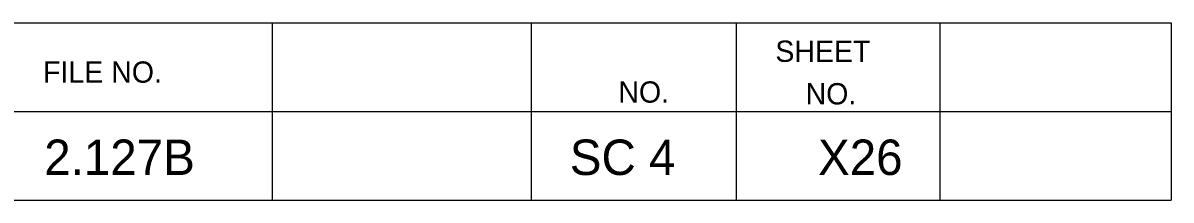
# Model space of a CAD drawing. Extents: x 1000 to 1162, y 999 to 8520.
# Drawn here: x 1145.41 to 1161.56, y 3975.05 to 3977.55 of the extents above; entities that cross this region are included whole.
import ezdxf

# ---------------------------------------------------------------- set-up
doc = ezdxf.new("R2010")
doc.units = 0
doc.layers.add('Level 20', color=7, linetype='Continuous')
doc.layers.add('Level 3', color=7, linetype='Continuous')

msp = doc.modelspace()

# ---------------------------------------------------------------- linework, layer by layer
at = {"layer": 'Level 3'}
for p, q in [((1133.055, 3977.546), (1161.555, 3977.546)), ((1133.055, 3977.546), (1161.555, 3977.546)), ((1133.055, 3977.546), (1161.555, 3977.546)), ((1133.055, 3977.546), (1161.555, 3977.546)), ((1133.055, 3977.546), (1161.555, 3977.546)), ((1133.055, 3977.546), (1161.555, 3977.546)), ((1133.055, 3977.546), (1161.555, 3977.546)), ((1133.055, 3977.546), (1161.555, 3977.546)), ((1133.055, 3977.546), (1161.555, 3977.546)), ((1133.055, 3977.546), (1161.555, 3977.546)), ((1133.055, 3977.546), (1161.555, 3977.546)), ((1133.055, 3977.546), (1161.555, 3977.546)), ((1133.055, 3977.546), (1161.555, 3977.546)), ((1133.055, 3977.546), (1161.555, 3977.546)), ((1133.055, 3977.546), (1161.555, 3977.546)), ((1133.055, 3977.546), (1161.555, 3977.546)), ((1133.055, 3977.546), (1161.555, 3977.546)), ((1133.055, 3977.546), (1161.555, 3977.546)), ((1133.055, 3977.546), (1161.555, 3977.546)), ((1133.055, 3977.546), (1161.555, 3977.546)), ((1133.055, 3977.546), (1161.555, 3977.546)), ((1133.055, 3977.546), (1161.555, 3977.546)), ((1133.055, 3977.546), (1161.555, 3977.546)), ((1133.055, 3977.546), (1161.555, 3977.546)), ((1148.913, 3977.546), (1148.913, 3975.046)), ((1148.913, 3977.546), (1148.913, 3975.046)), ((1148.913, 3977.546), (1148.913, 3975.046)), ((1148.913, 3977.546), (1148.913, 3975.046)), ((1148.913, 3977.546), (1148.913, 3975.046)), ((1148.913, 3977.546), (1148.913, 3975.046)), ((1148.913, 3977.546), (1148.913, 3975.046)), ((1148.913, 3977.546), (1148.913, 3975.046)), ((1148.913, 3977.546), (1148.913, 3975.046)), ((1148.913, 3977.546), (1148.913, 3975.046)), ((1148.913, 3977.546), (1148.913, 3975.046)), ((1148.913, 3977.546), (1148.913, 3975.046)), ((1148.913, 3977.546), (1148.913, 3975.046)), ((1148.913, 3977.546), (1148.913, 3975.046)), ((1148.913, 3977.546), (1148.913, 3975.046)), ((1148.913, 3977.546), (1148.913, 3975.046)), ((1148.913, 3977.546), (1148.913, 3975.046)), ((1148.913, 3977.546), (1148.913, 3975.046)), ((1148.913, 3977.546), (1148.913, 3975.046)), ((1148.913, 3977.546), (1148.913, 3975.046)), ((1148.913, 3977.546), (1148.913, 3975.046)), ((1148.913, 3977.546), (1148.913, 3975.046)), ((1148.913, 3977.546), (1148.913, 3975.046)), ((1148.913, 3977.546), (1148.913, 3975.046)), ((1152.554, 3977.546), (1152.554, 3975.046)), ((1152.554, 3977.546), (1152.554, 3975.046)), ((1152.554, 3977.546), (1152.554, 3975.046)), ((1152.554, 3977.546), (1152.554, 3975.046)), ((1152.554, 3977.546), (1152.554, 3975.046)), ((1152.554, 3977.546), (1152.554, 3975.046)), ((1152.554, 3977.546), (1152.554, 3975.046)), ((1152.554, 3977.546), (1152.554, 3975.046)), ((1152.554, 3977.546), (1152.554, 3975.046)), ((1152.554, 3977.546), (1152.554, 3975.046)), ((1152.554, 3977.546), (1152.554, 3975.046)), ((1152.554, 3977.546), (1152.554, 3975.046)), ((1152.554, 3977.546), (1152.554, 3975.046)), ((1152.554, 3977.546), (1152.554, 3975.046)), ((1152.554, 3977.546), (1152.554, 3975.046)), ((1152.554, 3977.546), (1152.554, 3975.046)), ((1152.554, 3977.546), (1152.554, 3975.046)), ((1152.554, 3977.546), (1152.554, 3975.046)), ((1152.554, 3977.546), (1152.554, 3975.046)), ((1152.554, 3977.546), (1152.554, 3975.046)), ((1152.554, 3977.546), (1152.554, 3975.046)), ((1152.554, 3977.546), (1152.554, 3975.046)), ((1152.554, 3977.546), (1152.554, 3975.046)), ((1152.554, 3977.546), (1152.554, 3975.046)), ((1155.44, 3977.546), (1155.44, 3975.046)), ((1155.44, 3977.546), (1155.44, 3975.046)), ((1155.44, 3977.546), (1155.44, 3975.046)), ((1155.44, 3977.546), (1155.44, 3975.046)), ((1155.44, 3977.546), (1155.44, 3975.046)), ((1155.44, 3977.546), (1155.44, 3975.046)), ((1155.44, 3977.546), (1155.44, 3975.046)), ((1155.44, 3977.546), (1155.44, 3975.046)), ((1155.44, 3977.546), (1155.44, 3975.046)), ((1155.44, 3977.546), (1155.44, 3975.046)), ((1155.44, 3977.546), (1155.44, 3975.046)), ((1155.44, 3977.546), (1155.44, 3975.046)), ((1155.44, 3977.546), (1155.44, 3975.046)), ((1155.44, 3977.546), (1155.44, 3975.046)), ((1155.44, 3977.546), (1155.44, 3975.046)), ((1155.44, 3977.546), (1155.44, 3975.046)), ((1155.44, 3977.546), (1155.44, 3975.046)), ((1155.44, 3977.546), (1155.44, 3975.046)), ((1155.44, 3977.546), (1155.44, 3975.046)), ((1155.44, 3977.546), (1155.44, 3975.046)), ((1155.44, 3977.546), (1155.44, 3975.046)), ((1155.44, 3977.546), (1155.44, 3975.046)), ((1155.44, 3977.546), (1155.44, 3975.046)), ((1155.44, 3977.546), (1155.44, 3975.046)), ((1158.305, 3977.546), (1158.305, 3975.046)), ((1158.305, 3977.546), (1158.305, 3975.046)), ((1158.305, 3977.546), (1158.305, 3975.046)), ((1158.305, 3977.546), (1158.305, 3975.046)), ((1158.305, 3977.546), (1158.305, 3975.046)), ((1158.305, 3977.546), (1158.305, 3975.046)), ((1158.305, 3977.546), (1158.305, 3975.046)), ((1158.305, 3977.546), (1158.305, 3975.046)), ((1158.305, 3977.546), (1158.305, 3975.046)), ((1158.305, 3977.546), (1158.305, 3975.046)), ((1158.305, 3977.546), (1158.305, 3975.046)), ((1158.305, 3977.546), (1158.305, 3975.046)), ((1158.305, 3977.546), (1158.305, 3975.046)), ((1158.305, 3977.546), (1158.305, 3975.046)), ((1158.305, 3977.546), (1158.305, 3975.046)), ((1158.305, 3977.546), (1158.305, 3975.046)), ((1158.305, 3977.546), (1158.305, 3975.046)), ((1158.305, 3977.546), (1158.305, 3975.046)), ((1158.305, 3977.546), (1158.305, 3975.046)), ((1158.305, 3977.546), (1158.305, 3975.046)), ((1158.305, 3977.546), (1158.305, 3975.046)), ((1158.305, 3977.546), (1158.305, 3975.046)), ((1158.305, 3977.546), (1158.305, 3975.046)), ((1158.305, 3977.546), (1158.305, 3975.046)), ((1161.555, 3977.546), (1161.555, 3975.046)), ((1161.555, 3977.546), (1161.555, 3975.046)), ((1161.555, 3977.546), (1161.555, 3975.046)), ((1161.555, 3977.546), (1161.555, 3975.046)), ((1161.555, 3977.546), (1161.555, 3975.046)), ((1161.555, 3977.546), (1161.555, 3975.046)), ((1161.555, 3977.546), (1161.555, 3975.046)), ((1161.555, 3977.546), (1161.555, 3975.046)), ((1161.555, 3977.546), (1161.555, 3975.046)), ((1161.555, 3977.546), (1161.555, 3975.046)), ((1161.555, 3977.546), (1161.555, 3975.046)), ((1161.555, 3977.546), (1161.555, 3975.046)), ((1161.555, 3977.546), (1161.555, 3975.046)), ((1161.555, 3977.546), (1161.555, 3975.046)), ((1161.555, 3977.546), (1161.555, 3975.046)), ((1161.555, 3977.546), (1161.555, 3975.046)), ((1161.555, 3977.546), (1161.555, 3975.046)), ((1161.555, 3977.546), (1161.555, 3975.046)), ((1161.555, 3977.546), (1161.555, 3975.046)), ((1161.555, 3977.546), (1161.555, 3975.046)), ((1161.555, 3977.546), (1161.555, 3975.046)), ((1161.555, 3977.546), (1161.555, 3975.046)), ((1161.555, 3977.546), (1161.555, 3975.046)), ((1161.555, 3977.546), (1161.555, 3975.046)), ((1133.055, 3976.296), (1161.555, 3976.296)), ((1133.055, 3976.296), (1161.555, 3976.296)), ((1133.055, 3976.296), (1161.555, 3976.296)), ((1133.055, 3976.296), (1161.555, 3976.296)), ((1133.055, 3976.296), (1161.555, 3976.296)), ((1133.055, 3976.296), (1161.555, 3976.296)), ((1133.055, 3976.296), (1161.555, 3976.296)), ((1133.055, 3976.296), (1161.555, 3976.296)), ((1133.055, 3976.296), (1161.555, 3976.296)), ((1133.055, 3976.296), (1161.555, 3976.296)), ((1133.055, 3976.296), (1161.555, 3976.296)), ((1133.055, 3976.296), (1161.555, 3976.296)), ((1133.055, 3976.296), (1161.555, 3976.296)), ((1133.055, 3976.296), (1161.555, 3976.296)), ((1133.055, 3976.296), (1161.555, 3976.296)), ((1133.055, 3976.296), (1161.555, 3976.296)), ((1133.055, 3976.296), (1161.555, 3976.296)), ((1133.055, 3976.296), (1161.555, 3976.296)), ((1133.055, 3976.296), (1161.555, 3976.296)), ((1133.055, 3976.296), (1161.555, 3976.296)), ((1133.055, 3976.296), (1161.555, 3976.296)), ((1133.055, 3976.296), (1161.555, 3976.296)), ((1133.055, 3976.296), (1161.555, 3976.296)), ((1133.055, 3976.296), (1161.555, 3976.296)), ((1133.055, 3975.046), (1161.555, 3975.046)), ((1133.055, 3975.046), (1161.555, 3975.046)), ((1133.055, 3975.046), (1161.555, 3975.046)), ((1133.055, 3975.046), (1161.555, 3975.046)), ((1133.055, 3975.046), (1161.555, 3975.046)), ((1133.055, 3975.046), (1161.555, 3975.046)), ((1133.055, 3975.046), (1161.555, 3975.046)), ((1133.055, 3975.046), (1161.555, 3975.046)), ((1133.055, 3975.046), (1161.555, 3975.046)), ((1133.055, 3975.046), (1161.555, 3975.046)), ((1133.055, 3975.046), (1161.555, 3975.046)), ((1133.055, 3975.046), (1161.555, 3975.046)), ((1133.055, 3975.046), (1161.555, 3975.046)), ((1133.055, 3975.046), (1161.555, 3975.046)), ((1133.055, 3975.046), (1161.555, 3975.046)), ((1133.055, 3975.046), (1161.555, 3975.046)), ((1133.055, 3975.046), (1161.555, 3975.046)), ((1133.055, 3975.046), (1161.555, 3975.046)), ((1133.055, 3975.046), (1161.555, 3975.046)), ((1133.055, 3975.046), (1161.555, 3975.046)), ((1133.055, 3975.046), (1161.555, 3975.046)), ((1133.055, 3975.046), (1161.555, 3975.046)), ((1133.055, 3975.046), (1161.555, 3975.046)), ((1133.055, 3975.046), (1161.555, 3975.046))]:
    msp.add_line(p, q, dxfattribs=at)

# ---------------------------------------------------------------- texts
at = {"layer": 'Level 20'}
for s, p in [('2.127B', (1145.707, 3975.4)), ('SC 4', (1153.099, 3975.4)), ('X26', (1156.59, 3975.4))]:
    msp.add_text(s, height=0.5, dxfattribs=at).set_placement(p)
at = {"layer": 'Level 3'}
for s, p in [('SHEET', (1155.99, 3976.996)), ('SHEET', (1155.99, 3976.996)), ('SHEET', (1155.99, 3976.996)), ('SHEET', (1155.99, 3976.996)), ('SHEET', (1155.99, 3976.996)), ('SHEET', (1155.99, 3976.996)), ('SHEET', (1155.99, 3976.996)), ('SHEET', (1155.99, 3976.996)), ('SHEET', (1155.99, 3976.996)), ('SHEET', (1155.99, 3976.996)), ('SHEET', (1155.99, 3976.996)), ('SHEET', (1155.99, 3976.996)), ('SHEET', (1155.99, 3976.996)), ('SHEET', (1155.99, 3976.996)), ('SHEET', (1155.99, 3976.996)), ('SHEET', (1155.99, 3976.996)), ('SHEET', (1155.99, 3976.996)), ('SHEET', (1155.99, 3976.996)), ('SHEET', (1155.99, 3976.996)), ('SHEET', (1155.99, 3976.996)), ('SHEET', (1155.99, 3976.996)), ('SHEET', (1155.99, 3976.996)), ('SHEET', (1155.99, 3976.996)), ('SHEET', (1155.99, 3976.996)), ('FILE NO.', (1145.691, 3976.702)), ('FILE NO.', (1145.691, 3976.702)), ('FILE NO.', (1145.691, 3976.702)), ('FILE NO.', (1145.691, 3976.702)), ('FILE NO.', (1145.691, 3976.702)), ('FILE NO.', (1145.691, 3976.702)), ('FILE NO.', (1145.691, 3976.702)), ('FILE NO.', (1145.691, 3976.702)), ('FILE NO.', (1145.691, 3976.702)), ('FILE NO.', (1145.691, 3976.702)), ('FILE NO.', (1145.691, 3976.702)), ('FILE NO.', (1145.691, 3976.702)), ('FILE NO.', (1145.691, 3976.702)), ('FILE NO.', (1145.691, 3976.702)), ('FILE NO.', (1145.691, 3976.702)), ('FILE NO.', (1145.691, 3976.702)), ('FILE NO.', (1145.691, 3976.702)), ('FILE NO.', (1145.691, 3976.702)), ('FILE NO.', (1145.691, 3976.702)), ('FILE NO.', (1145.691, 3976.702)), ('FILE NO.', (1145.691, 3976.702)), ('FILE NO.', (1145.691, 3976.702)), ('FILE NO.', (1145.691, 3976.702)), ('FILE NO.', (1145.691, 3976.702)), ('NO.', (1153.782, 3976.421)), ('NO.', (1153.782, 3976.421)), ('NO.', (1153.782, 3976.421)), ('NO.', (1153.782, 3976.421)), ('NO.', (1153.782, 3976.421)), ('NO.', (1153.782, 3976.421)), ('NO.', (1153.782, 3976.421)), ('NO.', (1153.782, 3976.421)), ('NO.', (1153.782, 3976.421)), ('NO.', (1153.782, 3976.421)), ('NO.', (1153.782, 3976.421)), ('NO.', (1153.782, 3976.421)), ('NO.', (1153.782, 3976.421)), ('NO.', (1153.782, 3976.421)), ('NO.', (1153.782, 3976.421)), ('NO.', (1153.782, 3976.421)), ('NO.', (1153.782, 3976.421)), ('NO.', (1153.782, 3976.421)), ('NO.', (1153.782, 3976.421)), ('NO.', (1153.782, 3976.421)), ('NO.', (1153.782, 3976.421)), ('NO.', (1153.782, 3976.421)), ('NO.', (1153.782, 3976.421)), ('NO.', (1153.782, 3976.421)), ('NO.', (1156.415, 3976.396)), ('NO.', (1156.415, 3976.396)), ('NO.', (1156.415, 3976.396)), ('NO.', (1156.415, 3976.396)), ('NO.', (1156.415, 3976.396)), ('NO.', (1156.415, 3976.396)), ('NO.', (1156.415, 3976.396)), ('NO.', (1156.415, 3976.396)), ('NO.', (1156.415, 3976.396)), ('NO.', (1156.415, 3976.396)), ('NO.', (1156.415, 3976.396)), ('NO.', (1156.415, 3976.396)), ('NO.', (1156.415, 3976.396)), ('NO.', (1156.415, 3976.396)), ('NO.', (1156.415, 3976.396)), ('NO.', (1156.415, 3976.396)), ('NO.', (1156.415, 3976.396)), ('NO.', (1156.415, 3976.396)), ('NO.', (1156.415, 3976.396)), ('NO.', (1156.415, 3976.396)), ('NO.', (1156.415, 3976.396)), ('NO.', (1156.415, 3976.396)), ('NO.', (1156.415, 3976.396)), ('NO.', (1156.415, 3976.396))]:
    msp.add_text(s, height=0.3, dxfattribs=at).set_placement(p)

doc.saveas('drawing.dxf')
